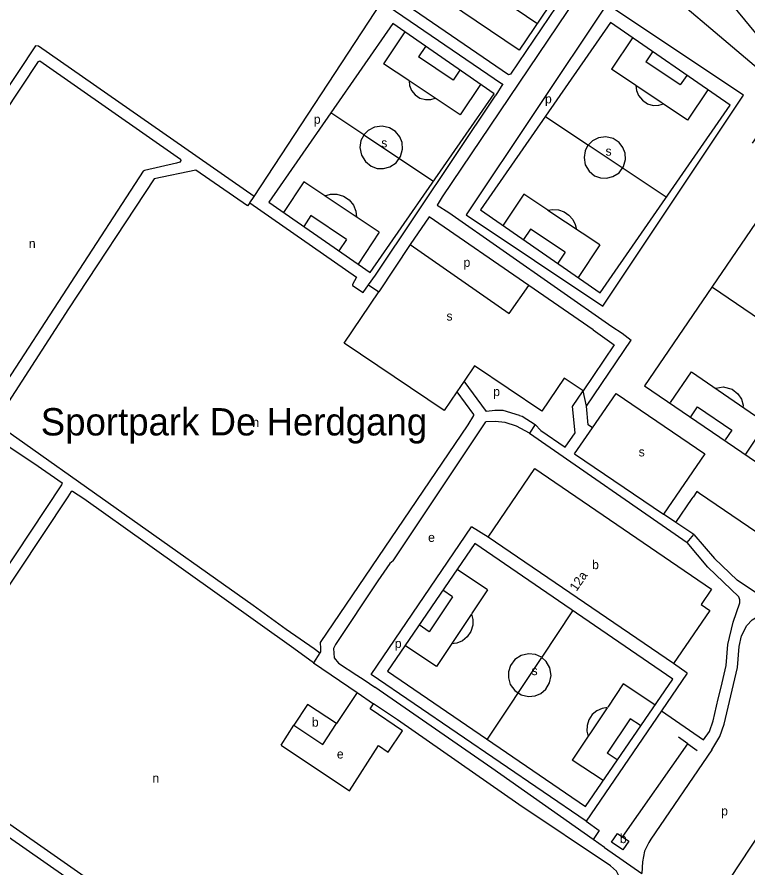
# Model space of a CAD drawing. Extents: x 157155 to 159285, y 385001 to 386651.
# Drawn here: x 158344.8 to 158665.4, y 385603.8 to 385977 of the extents above; entities that cross this region are included whole.
import ezdxf

# ---------------------------------------------------------------- set-up
doc = ezdxf.new("R2010")
doc.units = 0
for name, color, linetype in [('BLT_Basislijn', 7, 'Continuous'), ('BLT_Bebouwing', 7, 'Continuous'), ('BLT_Centroide', 7, 'Continuous'), ('BLT_Huisnummer', 7, 'Continuous'), ('BLT_Sport_parknaam', 7, 'Continuous'), ('BLT_Vlakafsluiter', 7, 'Continuous')]:
    doc.layers.add(name, color=color, linetype=linetype)

msp = doc.modelspace()

# ---------------------------------------------------------------- linework, layer by layer
at = {"layer": 'BLT_Basislijn'}
for p, q in [((158448.74, 385898.35), (158504.83, 385983.72)), ((158572.81, 385974.15), (158559.18, 385983.37)), ((158514.8, 385970.46), (158505.52, 385956.54)), ((158614.65, 385967.94), (158605.45, 385954.15)), ((158523.98, 385964.1), (158520.89, 385959.48)), ((158623.5, 385961.8), (158620.53, 385957.34)), ((158536.09, 385949.34), (158520.89, 385959.48)), ((158516.68, 385949.1), (158505.52, 385956.54)), ((158635.68, 385947.24), (158620.53, 385957.34)), ((158538.99, 385953.69), (158536.09, 385949.34)), ((158616.18, 385947), (158605.45, 385954.15)), ((158638.47, 385951.42), (158635.68, 385947.24)), ((158539.17, 385934.1), (158516.74, 385949.06)), ((158548.05, 385947.41), (158539.17, 385934.1)), ((158638.9, 385931.84), (158616.2, 385946.98)), ((158647.69, 385945.03), (158638.9, 385931.84)), ((158501.94, 385863.79), (158554.76, 385942.71)), ((158496.84, 385925.27), (158482.38, 385934.92)), ((158595.14, 385920.83), (158576.49, 385933.27)), ((158527.39, 385904.89), (158496.88, 385925.24)), ((158629.47, 385897.93), (158595.2, 385920.79)), ((158470.63, 385904.65), (158461.72, 385891.29)), ((158479.77, 385898.55), (158470.63, 385904.65)), ((158446.84, 385895.45), (158448.74, 385898.35)), ((158503.68, 385882.6), (158479.88, 385898.48)), ((158567.01, 385899.28), (158557.93, 385885.66)), ((158577.56, 385892.25), (158567.01, 385899.28)), ((158446.84, 385895.45), (158493.66, 385862.92)), ((158600.34, 385877.05), (158577.65, 385892.19)), ((158473.65, 385889.91), (158470.5, 385885.2)), ((158489.29, 385879.48), (158473.65, 385889.91)), ((158569.97, 385883.95), (158566.94, 385879.41)), ((158585.13, 385873.84), (158569.97, 385883.95)), ((158503.68, 385882.6), (158494.37, 385868.65)), ((158489.29, 385879.48), (158485.96, 385874.49)), ((158600.34, 385877.05), (158590.86, 385862.82)), ((158585.13, 385873.84), (158581.92, 385869.02)), ((158498.99, 385859.48), (158501.94, 385863.79)), ((158498.99, 385859.48), (158503.42, 385856.41)), ((158597.39, 385839.81), (158569.25, 385859.31)), ((158649.78, 385858.51), (158705.22, 385820.8)), ((158610.2, 385838.34), (158614.17, 385835.29)), ((158509.68, 385738.41), (158550.35, 385799.38)), ((158554.53, 385799.55), (158550.35, 385799.38)), ((158558.8, 385799.09), (158554.53, 385799.55)), ((158563.88, 385797.6), (158558.8, 385799.09)), ((158569.52, 385794.45), (158563.88, 385797.6)), ((158572.08, 385798.25), (158569.52, 385794.45)), ((158569.52, 385794.45), (158638.61, 385746.58)), ((158589.33, 385785.45), (158597.19, 385796.86)), ((158589.33, 385785.45), (158628.3, 385758.98)), ((158633.71, 385755.24), (158628.3, 385758.98)), ((158638.61, 385746.58), (158641.67, 385750)), ((158641.67, 385750), (158650.61, 385739.48)), ((158647.74, 385735.72), (158638.61, 385746.58)), ((158551.18, 385725.78), (158537.81, 385734.7)), ((158535.81, 385722.7), (158531.54, 385725.55)), ((158551.18, 385725.78), (158544.14, 385715.22)), ((158535.81, 385722.7), (158525.59, 385707.37)), ((158588.46, 385716.61), (158574.9, 385696.28)), ((158543.99, 385714.99), (158528.71, 385692.08)), ((158525.59, 385707.37), (158521.13, 385710.34)), ((158528.71, 385692.08), (158514.92, 385701.27)), ((158477.61, 385698.12), (158474.88, 385693.78)), ((158474.88, 385693.78), (158493.97, 385680.68)), ((158574.8, 385696.14), (158550.9, 385660.29)), ((158638.73, 385689.24), (158632.74, 385693.43)), ((158497.06, 385686.35), (158501.77, 385683.03)), ((158638.73, 385689.24), (158627.44, 385672.75)), ((158505.57, 385680.38), (158501.77, 385683.03)), ((158610.65, 385684.58), (158603.82, 385674.35)), ((158624.53, 385675.32), (158610.65, 385684.58)), ((158652.32, 385677.88), (158653.57, 385683.06)), ((158493.97, 385680.68), (158484.96, 385667.09)), ((158493.97, 385680.68), (158501.1, 385675.77)), ((158553.02, 385647.56), (158505.57, 385680.38)), ((158603.61, 385674.03), (158588.32, 385651.11)), ((158613.68, 385669.24), (158603.58, 385654.09)), ((158618.26, 385666.18), (158613.68, 385669.24)), ((158460.59, 385657.57), (158466.18, 385666.41)), ((158638.98, 385658.23), (158634.89, 385661.11)), ((158610.4, 385617.62), (158638.98, 385658.23)), ((158638.98, 385658.23), (158643.07, 385655.35)), ((158607.98, 385651.16), (158603.58, 385654.09)), ((158601.79, 385642.12), (158588.32, 385651.11)), ((158597.44, 385616.3), (158553.02, 385647.56)), ((158602.47, 385612.76), (158597.44, 385616.3)), ((158602.47, 385612.76), (158618.75, 385601.38))]:
    msp.add_line(p, q, dxfattribs=at)
for points in [[(158522.06, 386149.41), (158522.79, 386148.46), (158651.38, 385990.95), (158756.98, 385862.92)], [(158601.59, 386011.77), (158561.14, 385951.93), (158560.35, 385951.65), (158448.74, 386028.15)], [(158605.54, 386008.81), (158602.79, 386004.25), (158531.21, 385898.12), (158528.99, 385894.46), (158534.09, 385891.2), (158605.58, 385841.25), (158610.2, 385838.34)], [(158667.29, 385921.7), (158682.04, 385942.77), (158682.27, 385943.78), (158605.54, 386008.81)], [(158504.83, 385983.72), (158557.27, 385947.82), (158557.8, 385947.74), (158554.76, 385942.71)], [(158448.74, 385898.35), (158354.15, 385964.28), (158352.94, 385964.44), (158268.74, 385837.47)], [(158336.45, 385811.67), (158330.11, 385802.42), (158329.64, 385802.42), (158279.34, 385836.19), (158275.74, 385838.33), (158275.74, 385838.74), (158315.86, 385899.92), (158354.15, 385957.43), (158354.79, 385957.75), (158416.49, 385914.72), (158416.65, 385914.02), (158416.12, 385913.34), (158414.67, 385912.91), (158400.72, 385909.7), (158400.11, 385909.34), (158336.45, 385811.67)], [(158516.72, 385949.07), (158516.96, 385946.99), (158517.83, 385944.84), (158519.39, 385942.9), (158521.5, 385941.49), (158523.89, 385940.8), (158526.21, 385940.82), (158528.22, 385941.4)], [(158616.19, 385946.99), (158616.46, 385944.79), (158617.4, 385942.52), (158619.04, 385940.49), (158621.27, 385939), (158623.78, 385938.27), (158626.23, 385938.28), (158628.36, 385938.87)], [(158496.88, 385925.23), (158495.64, 385922.78), (158495.16, 385919.71), (158495.8, 385916.44), (158497.57, 385913.57), (158500.08, 385911.6), (158502.79, 385910.64), (158505.45, 385910.52), (158508.34, 385911.29), (158511.05, 385913.12), (158513.01, 385915.88), (158513.85, 385919.04), (158513.63, 385922.03), (158512.64, 385924.5), (158510.84, 385926.74), (158508.15, 385928.46), (158504.86, 385929.19), (158501.56, 385928.72), (158498.83, 385927.26), (158496.92, 385925.29)], [(158595.18, 385920.74), (158593.94, 385918.37), (158593.44, 385915.39), (158594.01, 385912.2), (158595.68, 385909.38), (158598.1, 385907.42), (158600.72, 385906.45), (158603.3, 385906.29), (158606.13, 385906.99), (158608.8, 385908.74), (158610.75, 385911.39), (158611.62, 385914.46), (158611.44, 385917.36), (158610.52, 385919.79), (158608.81, 385922), (158606.22, 385923.72), (158603.03, 385924.47), (158599.81, 385924.06), (158597.12, 385922.69), (158595.23, 385920.8)], [(158446.84, 385895.45), (158445.84, 385894.24), (158423.17, 385909.89), (158404.88, 385906), (158367.32, 385849.04), (158335.06, 385799.16), (158448.39, 385719.01), (158462.84, 385708.45), (158475.15, 385700), (158477.61, 385698.12)], [(158479.81, 385898.53), (158482.23, 385899.25), (158485.04, 385899.31), (158487.93, 385898.49), (158490.5, 385896.78), (158492.37, 385894.42), (158493.4, 385891.8), (158493.66, 385889.29)], [(158577.59, 385892.22), (158579.81, 385892.61), (158582.25, 385892.44), (158584.68, 385891.62), (158586.85, 385890.17), (158588.54, 385888.24), (158589.63, 385886.06), (158590.13, 385883.86)], [(158569.25, 385859.31), (158525.59, 385889.41), (158517.15, 385877.17)], [(158517.15, 385877.17), (158503.42, 385856.41)], [(158517.15, 385877.17), (158560.69, 385846.97), (158569.25, 385859.31)], [(158493.66, 385862.92), (158491.87, 385859.64), (158491.94, 385859.22), (158496.54, 385856.2), (158498.99, 385859.48)], [(158537.72, 385812.68), (158532.11, 385804.36), (158488.26, 385833.95), (158503.42, 385856.41)], [(158597.39, 385839.81), (158606.73, 385833.26)], [(158594.48, 385806.3), (158614.17, 385835.29)], [(158606.73, 385833.26), (158593.08, 385813)], [(158284.29, 385826.3), (158352.15, 385781.34), (158364.58, 385772.64), (158364.32, 385771.75), (158316.66, 385700)], [(158545.4, 385824.06), (158540.87, 385817.34)], [(158593.08, 385813), (158584.76, 385818.61), (158575, 385804.12), (158545.4, 385824.06)], [(158631.35, 385807.94), (158640.63, 385821.39), (158673.35, 385798.82), (158664.31, 385785.2)], [(158540.87, 385817.34), (158537.72, 385812.68)], [(158565.17, 385802.25), (158558.02, 385804.45), (158554.29, 385804.48), (158550.61, 385804.03), (158540.87, 385817.34)], [(158537.72, 385812.68), (158544.92, 385802.64), (158544.92, 385802.16), (158542.44, 385798.09), (158477.77, 385702.61), (158477.88, 385700), (158477.83, 385698.55), (158477.61, 385698.12)], [(158589.57, 385794.61), (158588.35, 385806.12), (158593.08, 385813)], [(158651.26, 385814.17), (158654.54, 385814.82), (158658.41, 385813.72), (158660.92, 385811.79), (158662.46, 385809.34), (158663.23, 385806.83), (158663.28, 385806.21)], [(158597.19, 385796.86), (158607.6, 385811.88), (158646.43, 385785.44), (158628.3, 385758.98)], [(158597.19, 385796.86), (158595.33, 385798.14), (158594.48, 385806.3)], [(158640.33, 385801.68), (158643.28, 385805.99), (158658.23, 385795.75), (158655.33, 385791.51)], [(158565.17, 385802.25), (158566.31, 385801.87), (158572.08, 385798.25)], [(158572.08, 385798.25), (158574.44, 385795.7), (158585.22, 385788.28), (158589.57, 385794.61)], [(158402.08, 385745.85), (158374.16, 385765.71), (158369.08, 385768.96), (158368.6, 385768.88), (158367.01, 385766.57), (158322.72, 385700), (158307.24, 385677.11), (158293.76, 385656.59), (158293.8, 385656.25), (158431.03, 385560.34)], [(158669.25, 385750.95), (158644.07, 385768.05), (158642.98, 385768.9), (158641.27, 385766.41)], [(158633.71, 385755.24), (158640.88, 385765.87), (158641.27, 385766.41)], [(158594.32, 385624.25), (158500.05, 385688.62), (158544.11, 385753.35)], [(158551.44, 385748.89), (158544.11, 385753.35)], [(158641.67, 385750), (158633.71, 385755.24)], [(158474.88, 385693.78), (158466.23, 385700), (158402.08, 385745.85)], [(158509.68, 385738.41), (158508.3, 385737.35), (158503, 385729.66), (158484.49, 385701.82), (158483.6, 385700), (158483.92, 385695.9), (158485.83, 385693.52), (158493.85, 385688.4)], [(158650.61, 385739.48), (158660.66, 385730.07)], [(158661.4, 385722.64), (158647.74, 385735.72)], [(158745.66, 385672.03), (158705.44, 385700), (158660.66, 385730.07)], [(158653.57, 385683.06), (158655.83, 385692.52), (158656.5, 385701.73), (158658.9, 385711.57), (158661.71, 385720.03), (158661.82, 385721.4), (158661.4, 385722.64)], [(158544.05, 385715.08), (158544.65, 385712.8), (158544.63, 385710.2), (158543.84, 385707.55), (158542.27, 385705.2), (158540.12, 385703.44), (158537.73, 385702.43), (158535.4, 385702.11)], [(158649.5, 385655.57), (158653.02, 385661.39), (158654.84, 385666.9), (158660.79, 385691.75), (158661.46, 385700.95), (158662.57, 385705.53), (158664.82, 385710.07), (158667.15, 385712.61), (158669.42, 385713.88), (158671.86, 385714.34), (158673.57, 385714.2), (158675.12, 385713.5)], [(158574.75, 385696.23), (158572.24, 385697.38), (158569.15, 385697.75), (158565.9, 385697), (158563.08, 385695.14), (158561.18, 385692.55), (158560.3, 385689.81), (158560.27, 385687.14), (158561.13, 385684.26), (158563.05, 385681.6), (158565.87, 385679.71), (158569.07, 385678.96), (158572.05, 385679.27), (158574.51, 385680.33), (158576.71, 385682.19), (158578.36, 385684.93), (158579.01, 385688.25), (158578.45, 385691.55), (158576.92, 385694.26), (158574.9, 385696.13)], [(158493.85, 385688.4), (158497.06, 385686.35)], [(158460.59, 385657.57), (158490.59, 385637.65), (158503.34, 385657.51), (158507.53, 385654.58), (158513.89, 385663.94), (158499.69, 385673.52), (158501.1, 385675.77)], [(158605.06, 385604.69), (158564.85, 385631.66), (158511.71, 385668.78), (158501.1, 385675.77)], [(158627.44, 385672.75), (158645.79, 385660.02), (158648.5, 385663.66), (158650.03, 385668.27), (158652.32, 385677.88)], [(158627.44, 385672.75), (158594.32, 385624.25)], [(158603.69, 385674.15), (158601.43, 385673.77), (158599.13, 385672.74), (158597.09, 385671.03), (158595.58, 385668.76), (158594.78, 385666.22), (158594.71, 385663.7), (158595.23, 385661.46)], [(158428.12, 385556.08), (158390.45, 385582.34), (158365.78, 385599.95), (158289.97, 385652.86), (158288.7, 385653.5), (158241.27, 385580.62), (158241.42, 385580.02), (158404.93, 385483.98)], [(158649.5, 385655.57), (158622.82, 385616.45), (158621.85, 385614.95), (158619.99, 385611.07), (158619.13, 385606.43), (158618.75, 385601.38)], [(158679.75, 385633.1), (158657.37, 385599.21), (158657.38, 385598.9), (158662.19, 385595.07)], [(158594.32, 385624.25), (158600.06, 385620.21), (158597.44, 385616.3)], [(158552.82, 385517.63), (158559.78, 385527.78), (158608.05, 385598.05), (158608.71, 385600.34), (158607.67, 385602.42), (158605.06, 385604.69)]]:
    msp.add_lwpolyline(points, dxfattribs=at)
for points in [[(158516.51, 386078.63), (158603.66, 386019.63), (158564.95, 385962.46), (158477.81, 386021.46)], [(158603.48, 385982.71), (158541.79, 385890.22), (158601.72, 385850.25), (158663.41, 385942.74)], [(158509.54, 385974.17), (158455.17, 385895.77), (158499.71, 385864.89), (158554.08, 385943.29)], [(158605.1, 385974.63), (158548.09, 385892.41), (158600.51, 385856.07), (158657.52, 385938.28)], [(158620, 385815.23), (158675.89, 385777.15), (158735.13, 385864.09), (158679.25, 385902.17)], [(158545.53, 385746.07), (158507.23, 385690.13), (158594.03, 385630.7), (158632.33, 385686.64)]]:
    msp.add_lwpolyline(points, close=True, dxfattribs=at)
at = {"layer": 'BLT_Bebouwing'}
for p, q in [((158632.74, 385693.43), (158551.44, 385748.89)), ((158484.96, 385667.09), (158472.17, 385675.51))]:
    msp.add_line(p, q, dxfattribs=at)
for points in [[(158551.44, 385748.89), (158571.91, 385778.94), (158649.42, 385726.12), (158644.81, 385719.35), (158648.63, 385716.75), (158632.74, 385693.43)], [(158472.17, 385675.51), (158466.18, 385666.41)], [(158466.18, 385666.41), (158478.97, 385657.99), (158484.96, 385667.09)]]:
    msp.add_lwpolyline(points, dxfattribs=at)
msp.add_lwpolyline([(158605.54, 385615.05), (158608.14, 385618.84), (158613.06, 385615.45), (158610.46, 385611.67)], close=True, dxfattribs=at)
at = {"layer": 'BLT_Vlakafsluiter'}
msp.add_line((158594.48, 385806.3), (158593.08, 385813), dxfattribs=at)

# ---------------------------------------------------------------- texts
at = {"layer": 'BLT_Centroide'}
for s, p in [('p', (158576.33, 385939.14)), ('p', (158474.93, 385930.19)), ('s', (158504.52, 385919.84)), ('s', (158602.88, 385916.21)), ('n', (158349.98, 385875.68)), ('p', (158540.6, 385867.42)), ('s', (158533.13, 385843.85)), ('p', (158553.61, 385810.74)), ('n', (158447.98, 385797.25)), ('s', (158617.4, 385784.28)), ('e', (158525.08, 385746.78)), ('b', (158596.99, 385734.83)), ('p', (158510.46, 385700.25)), ('s', (158570.43, 385688.34)), ('b', (158474.1, 385665.74)), ('e', (158485.05, 385651.78)), ('n', (158404.14, 385641.17)), ('p', (158653.58, 385626.79)), ('b', (158609.15, 385614.67))]:
    msp.add_text(s, height=4, dxfattribs=at).set_placement(p)
at = {"layer": 'BLT_Huisnummer'}
msp.add_text('12a', height=4, rotation=55.7002, dxfattribs=at).set_placement((158590.14, 385724.8))
at = {"layer": 'BLT_Sport_parknaam'}
msp.add_text('Sportpark De Herdgang', height=12, dxfattribs=at).set_placement((158355.2, 385793.47))

doc.saveas('drawing.dxf')
